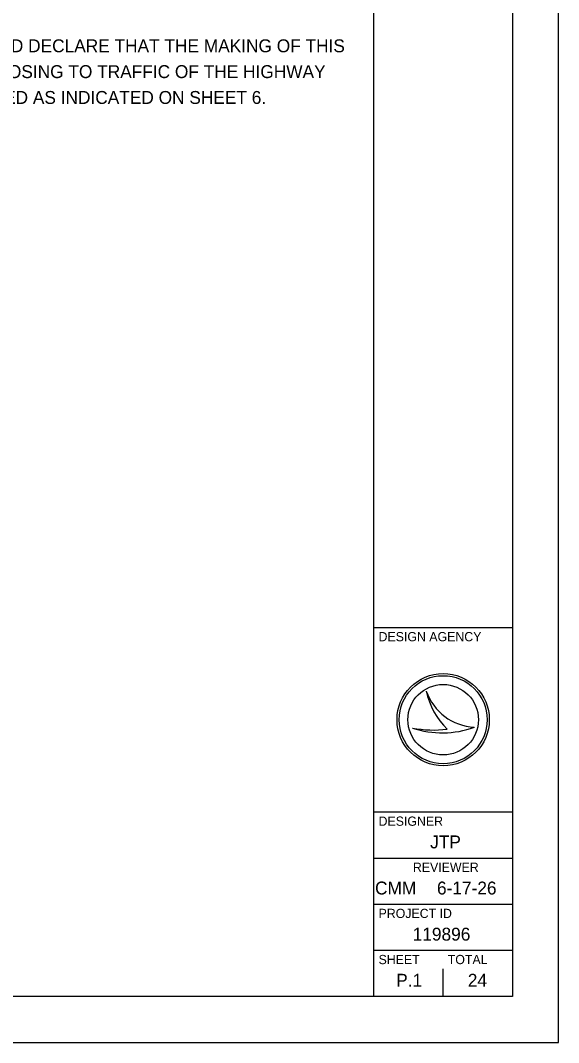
# Model space of a CAD drawing. Extents: x 36.7 to 70.7, y 0 to 22.
# Drawn here: x 64.86 to 70.69, y 0 to 11.08 of the extents above; entities that cross this region are included whole.
import ezdxf

# ---------------------------------------------------------------- set-up
doc = ezdxf.new("R2010")
doc.units = 0
for name, color, linetype in [('SH_Border', 7, 'Continuous'), ('SH_Cut_Line', 7, 'Continuous'), ('SH_Data', 7, 'Continuous')]:
    doc.layers.add(name, color=color, linetype=linetype)

msp = doc.modelspace()

# ---------------------------------------------------------------- linework, layer by layer
at = {"layer": 'SH_Border'}
for p, q in [((68.693, 0.497), (68.693, 21.497)), ((68.693, 4.497), (70.193, 4.497)), ((68.693, 2.497), (70.193, 2.497)), ((68.693, 1.997), (70.193, 1.997)), ((68.693, 1.497), (70.193, 1.497)), ((68.693, 0.997), (70.193, 0.997))]:
    msp.add_line(p, q, dxfattribs=at)
msp.add_lwpolyline([(38.193, 21.497), (70.193, 21.497), (70.193, 0.497), (38.193, 0.497)], close=True, dxfattribs=at)
at = {"layer": 'SH_Cut_Line'}
msp.add_lwpolyline([(36.693, -0.003), (70.693, -0.003), (70.693, 21.997), (36.693, 21.997)], close=True, dxfattribs=at)
at = {"layer": 'SH_Data'}
for p, q in [((69.261, 3.806), (69.261, 3.806)), ((69.443, 3.497), (69.443, 3.497)), ((69.111, 3.406), (69.111, 3.406)), ((69.781, 3.415), (69.781, 3.415)), ((69.443, 0.497), (69.443, 0.797)), ((69.068, 0.672), (69.068, 0.672))]:
    msp.add_line(p, q, dxfattribs=at)
for radius in [0.5, 0.477, 0.477, 0.382]:
    msp.add_circle((69.443, 3.497), radius, dxfattribs=at)
for centre, radius, start, end in [((69.809, 3.995), 0.58, 198.9257, 198.9319), ((70.04, 3.967), 0.796, 191.6379, 191.6421), ((69.809, 3.995), 0.58, 198.9319, 267.1657), ((70.04, 3.967), 0.796, 191.6421, 226.0947), ((69.433, 4.367), 1.013, 251.4576, 290.0832), ((69.341, 4.651), 1.266, 259.4964, 259.4995), ((69.433, 4.367), 1.013, 251.4527, 251.4576), ((69.341, 4.651), 1.266, 259.4995, 276.6672)]:
    msp.add_arc(centre, radius, start, end, dxfattribs=at)

# ---------------------------------------------------------------- texts
for s, height, p in [(' I HEREBY APPROVE THESE PLANS AND DECLARE THAT THE MAKING OF THIS', 0.14, (61.221, 10.732)), ('IMPROVEMENT WILL REQUIRE THE CLOSING TO TRAFFIC OF THE HIGHWAY', 0.14, (61.221, 10.452)), ('AND THAT DETOURS WILL BE PROVIDED AS INDICATED ON SHEET 6.', 0.14, (61.221, 10.172)), ('DESIGN AGENCY', 0.1, (68.743, 4.347)), ('DESIGNER', 0.1, (68.743, 2.347)), ('JTP', 0.14, (69.302, 2.102)), ('REVIEWER', 0.1, (69.115, 1.847)), ('CMM', 0.14, (68.705, 1.602)), ('6-17-26', 0.14, (69.376, 1.602)), ('PROJECT ID', 0.1, (68.743, 1.347)), ('119896', 0.14, (69.113, 1.102)), ('SHEET', 0.1, (68.743, 0.847)), ('TOTAL', 0.1, (69.493, 0.847)), ('P.1', 0.14, (68.934, 0.602)), ('24', 0.14, (69.71, 0.602))]:
    msp.add_text(s, height=height, dxfattribs=at).set_placement(p)

doc.saveas('drawing.dxf')
